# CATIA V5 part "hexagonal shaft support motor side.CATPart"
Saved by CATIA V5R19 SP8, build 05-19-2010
Part number: hexagonal shaft support motor side
Bounding box of the stored display mesh (mm): x -46.581 to -15.581, y 122.1 to 138.1, z -34.5 to -3.978
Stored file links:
  G:\EU_thinkMotion\CFAO_2010\MMS_groupe1\MMS_groupe1\A reprendre\gduval\CFAO kinematic ok\hexagonal shaft support motor side.CATPart
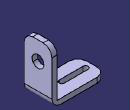
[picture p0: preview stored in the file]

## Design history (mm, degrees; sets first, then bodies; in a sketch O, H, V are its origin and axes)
Body1 (main body)
  Plane1: stored without definition
  Point1: stored without definition
  Plane2: type OffsetPt, RefPlane yz-plane, RefPoint Point1
  Line1: type Normal, RefPoint Point1, RefSkin Plane2, Start -20, End 20
  Plane3: stored without definition
  Plane4: type Offset, RefPlane Plane3, Offset 1, reversed
  Line2: stored without definition
  Sketch1 on Plane2, origin (-18.581, 0, 0), H (0, 1, 0), V (0, 0, 1)
    line L1 (138.1, -3.9782) -> (122.1, -3.9782)
    line L2 (122.1, -3.9782) -> (122.1, -34.5)
    line L3 (122.1, -34.5) -> (138.1, -34.5)
    line L4 (138.1, -34.5) -> (138.1, -3.9782)
    reference projected line E1 (130.1, -34.68) -> (130.1, 5.32) from Line2
    reference intersected line E2 through (0, -34.5) direction (-1, 0) from Plane1
    distance E1 L2 = 8
    distance L4 L2 = 16
    horizontal: L1 H, L3 H
    vertical: L2 V, L4 V
    coincidence: L3 E2
  Pad1: profile Sketch1, direction (1, 0, 0), length 3
  Sketch2 on start face of Pad1, origin (-18.581, 0, 0), H (0, -1, 0), V (0, 0, 1)
    line L1 (-138.1, -34.5) -> (-122.1, -34.5)
    line L2 (-122.1, -34.5) -> (-122.1, -31.5)
    line L3 (-122.1, -31.5) -> (-138.1, -31.5)
    line L4 (-138.1, -31.5) -> (-138.1, -34.5)
    reference projected line E1 (-122.1, -3.9782) -> (-122.1, -34.5) from edge [start face of Pad1 | face of Pad1 from Sketch1.L2]
    reference projected line E2 (-138.1, -34.5) -> (-138.1, -3.9782) from edge [start face of Pad1 | face of Pad1 from Sketch1.L4]
    reference projected line E3 (-122.1, -34.5) -> (-138.1, -34.5) from edge [start face of Pad1 | face of Pad1 from Sketch1.L3]
    distance L3 L1 = 3
    horizontal: L1 H, L3 H
    vertical: L2 V, L4 V
    coincidence: L2 E1, L4 E2, L1 E3
  Pad2: profile Sketch2, direction (-1, 0, 0), length 28
  Sketch3 on start face of Pad1, origin (-18.581, 130.1, -14.68), H (0, 1, 0), V (0, 0, -1)
    point P1 (0, 0)
    intersected point E1 (0, 0) from Line1
    coincidence: E1 P1
  Hole1: placed by Sketch3, at (-18.581, 130.1, -14.68) direction (1, 0, 0), diameter 7, through (limit type 6)
  Fillet1: radius 5, on edge [face of Pad1 from Sketch1.L1 | face of Pad2]; edge [face of Pad2 | face of Pad1 from Sketch1.L1]; edge [face of Pad2 | end face of Pad2] (x2)
  Sketch4 on face of Pad2 from Sketch2.L3, origin (0, 0, -31.5), H (1, 0, 0), V (0, 1, 0)
    construction line L1 (-42.9286, 130.1) -> (-29.1223, 130.1)
    line L2 (-42.9286, 131.6) -> (-29.1223, 131.6)
    line L3 (-29.1223, 128.6) -> (-42.9286, 128.6)
    arc A1 centre (-29.1223, 130.1) radius 1.5 from (-29.1223, 131.6) to (-29.1223, 128.6) cw
    arc A2 centre (-42.9286, 130.1) radius 1.5 from (-42.9286, 128.6) to (-42.9286, 131.6) cw
    reference projected line E1 (-38.581, 130.1) -> (1.419, 130.1) from Line1
    distance L1 L2 = 1.5
    horizontal: L1 H
    tangency: A1 L2, A2 L2, A1 L3, A2 L3
    coincidence: L1 E1
  Pocket1: profile Sketch4, direction (0, 0, -1), through (limit type 6)
  Fillet2: radius 5, on edge [face of Pad2 | end face of Pad1]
